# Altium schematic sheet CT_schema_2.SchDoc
size 591 x 347 mm
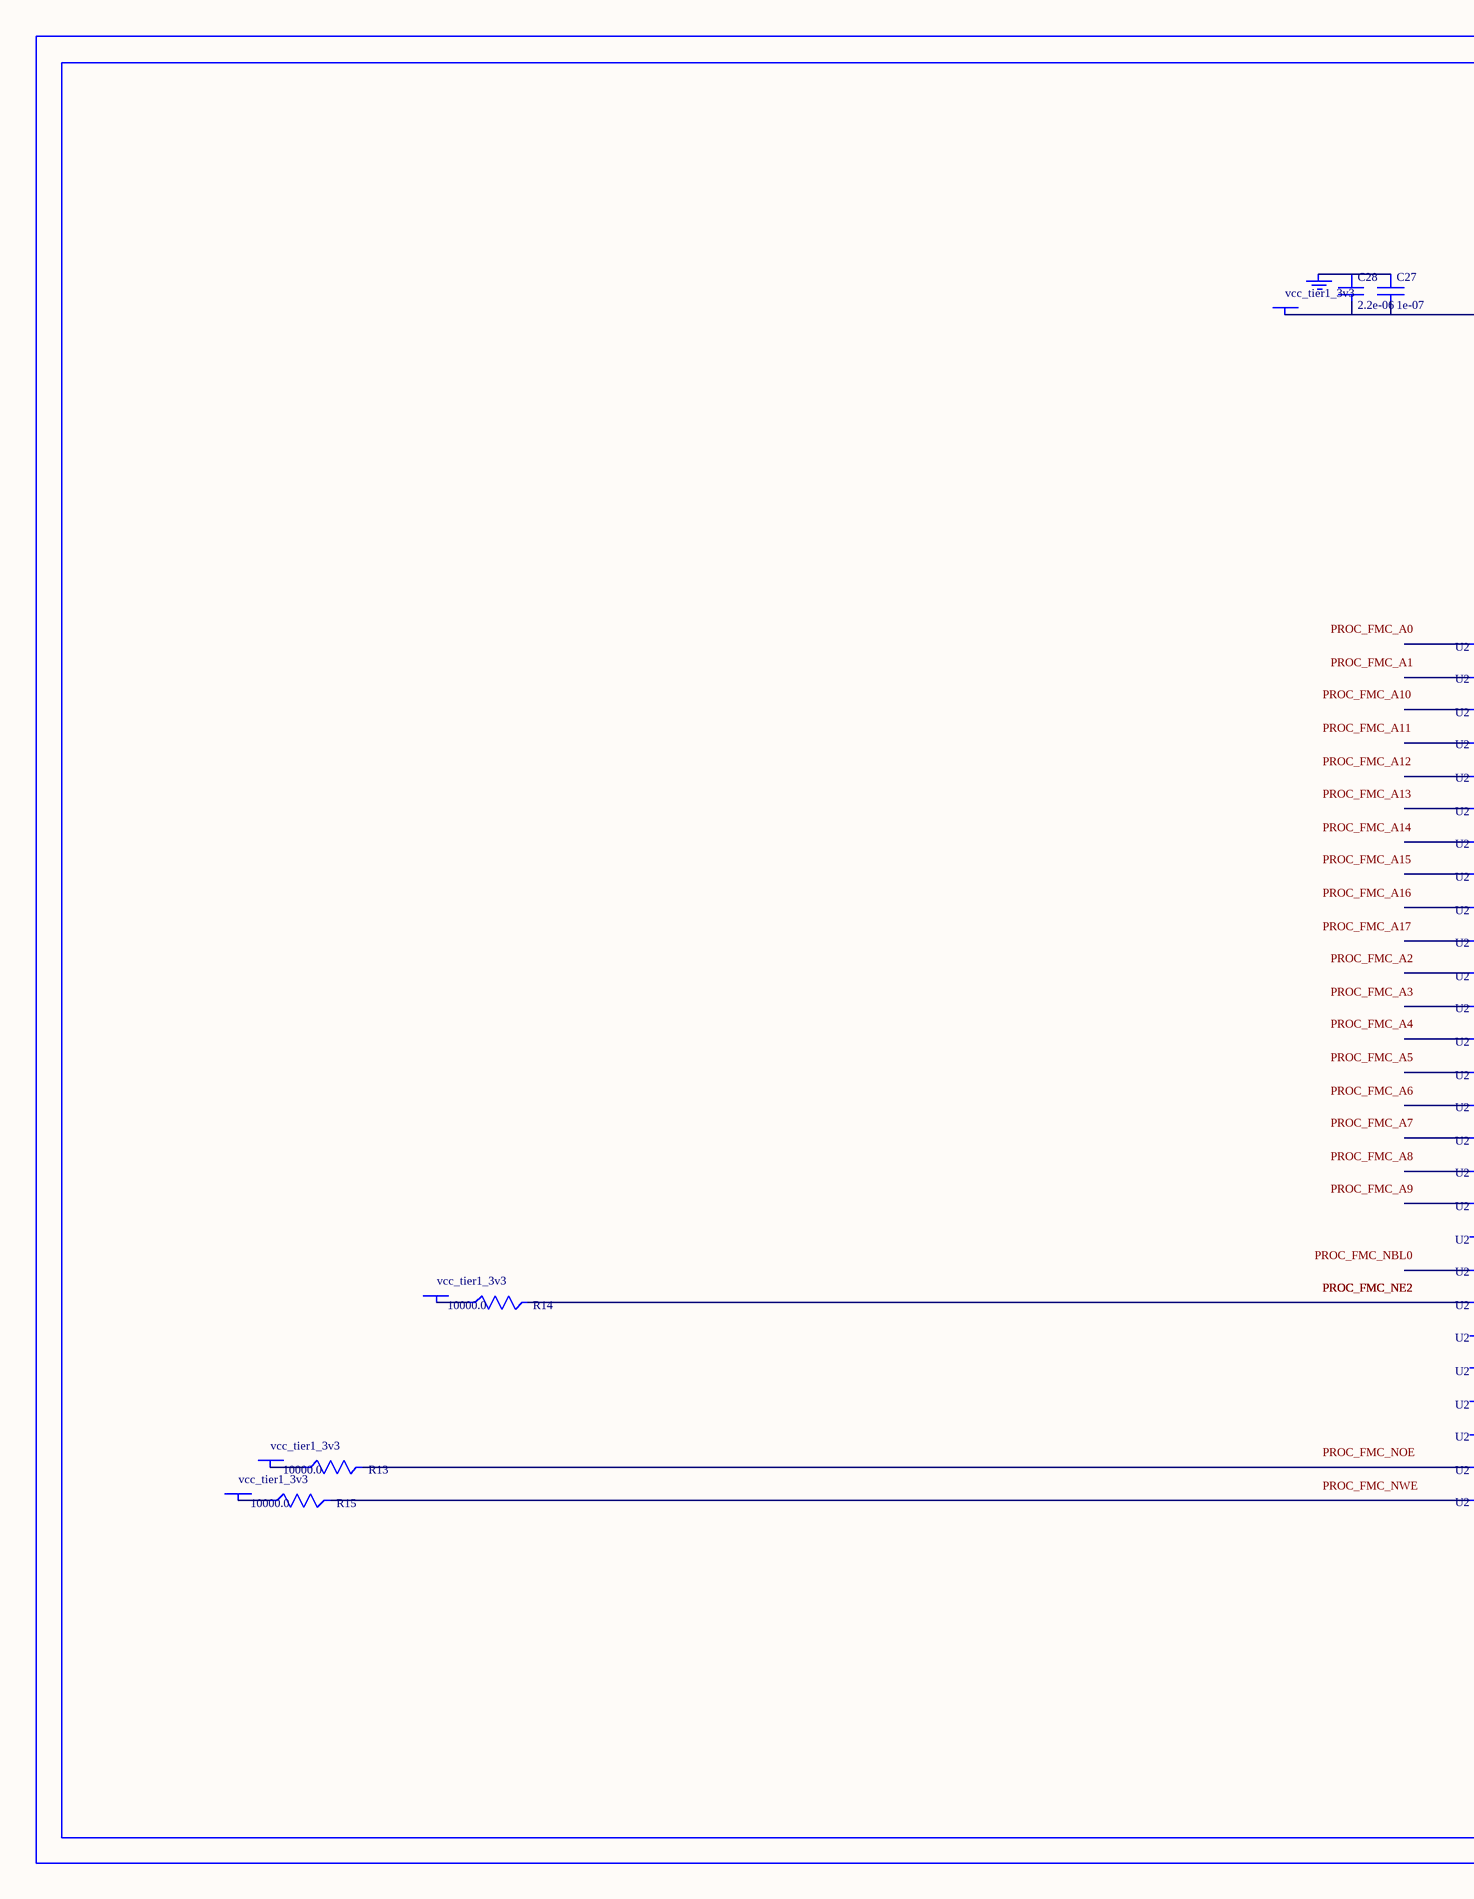
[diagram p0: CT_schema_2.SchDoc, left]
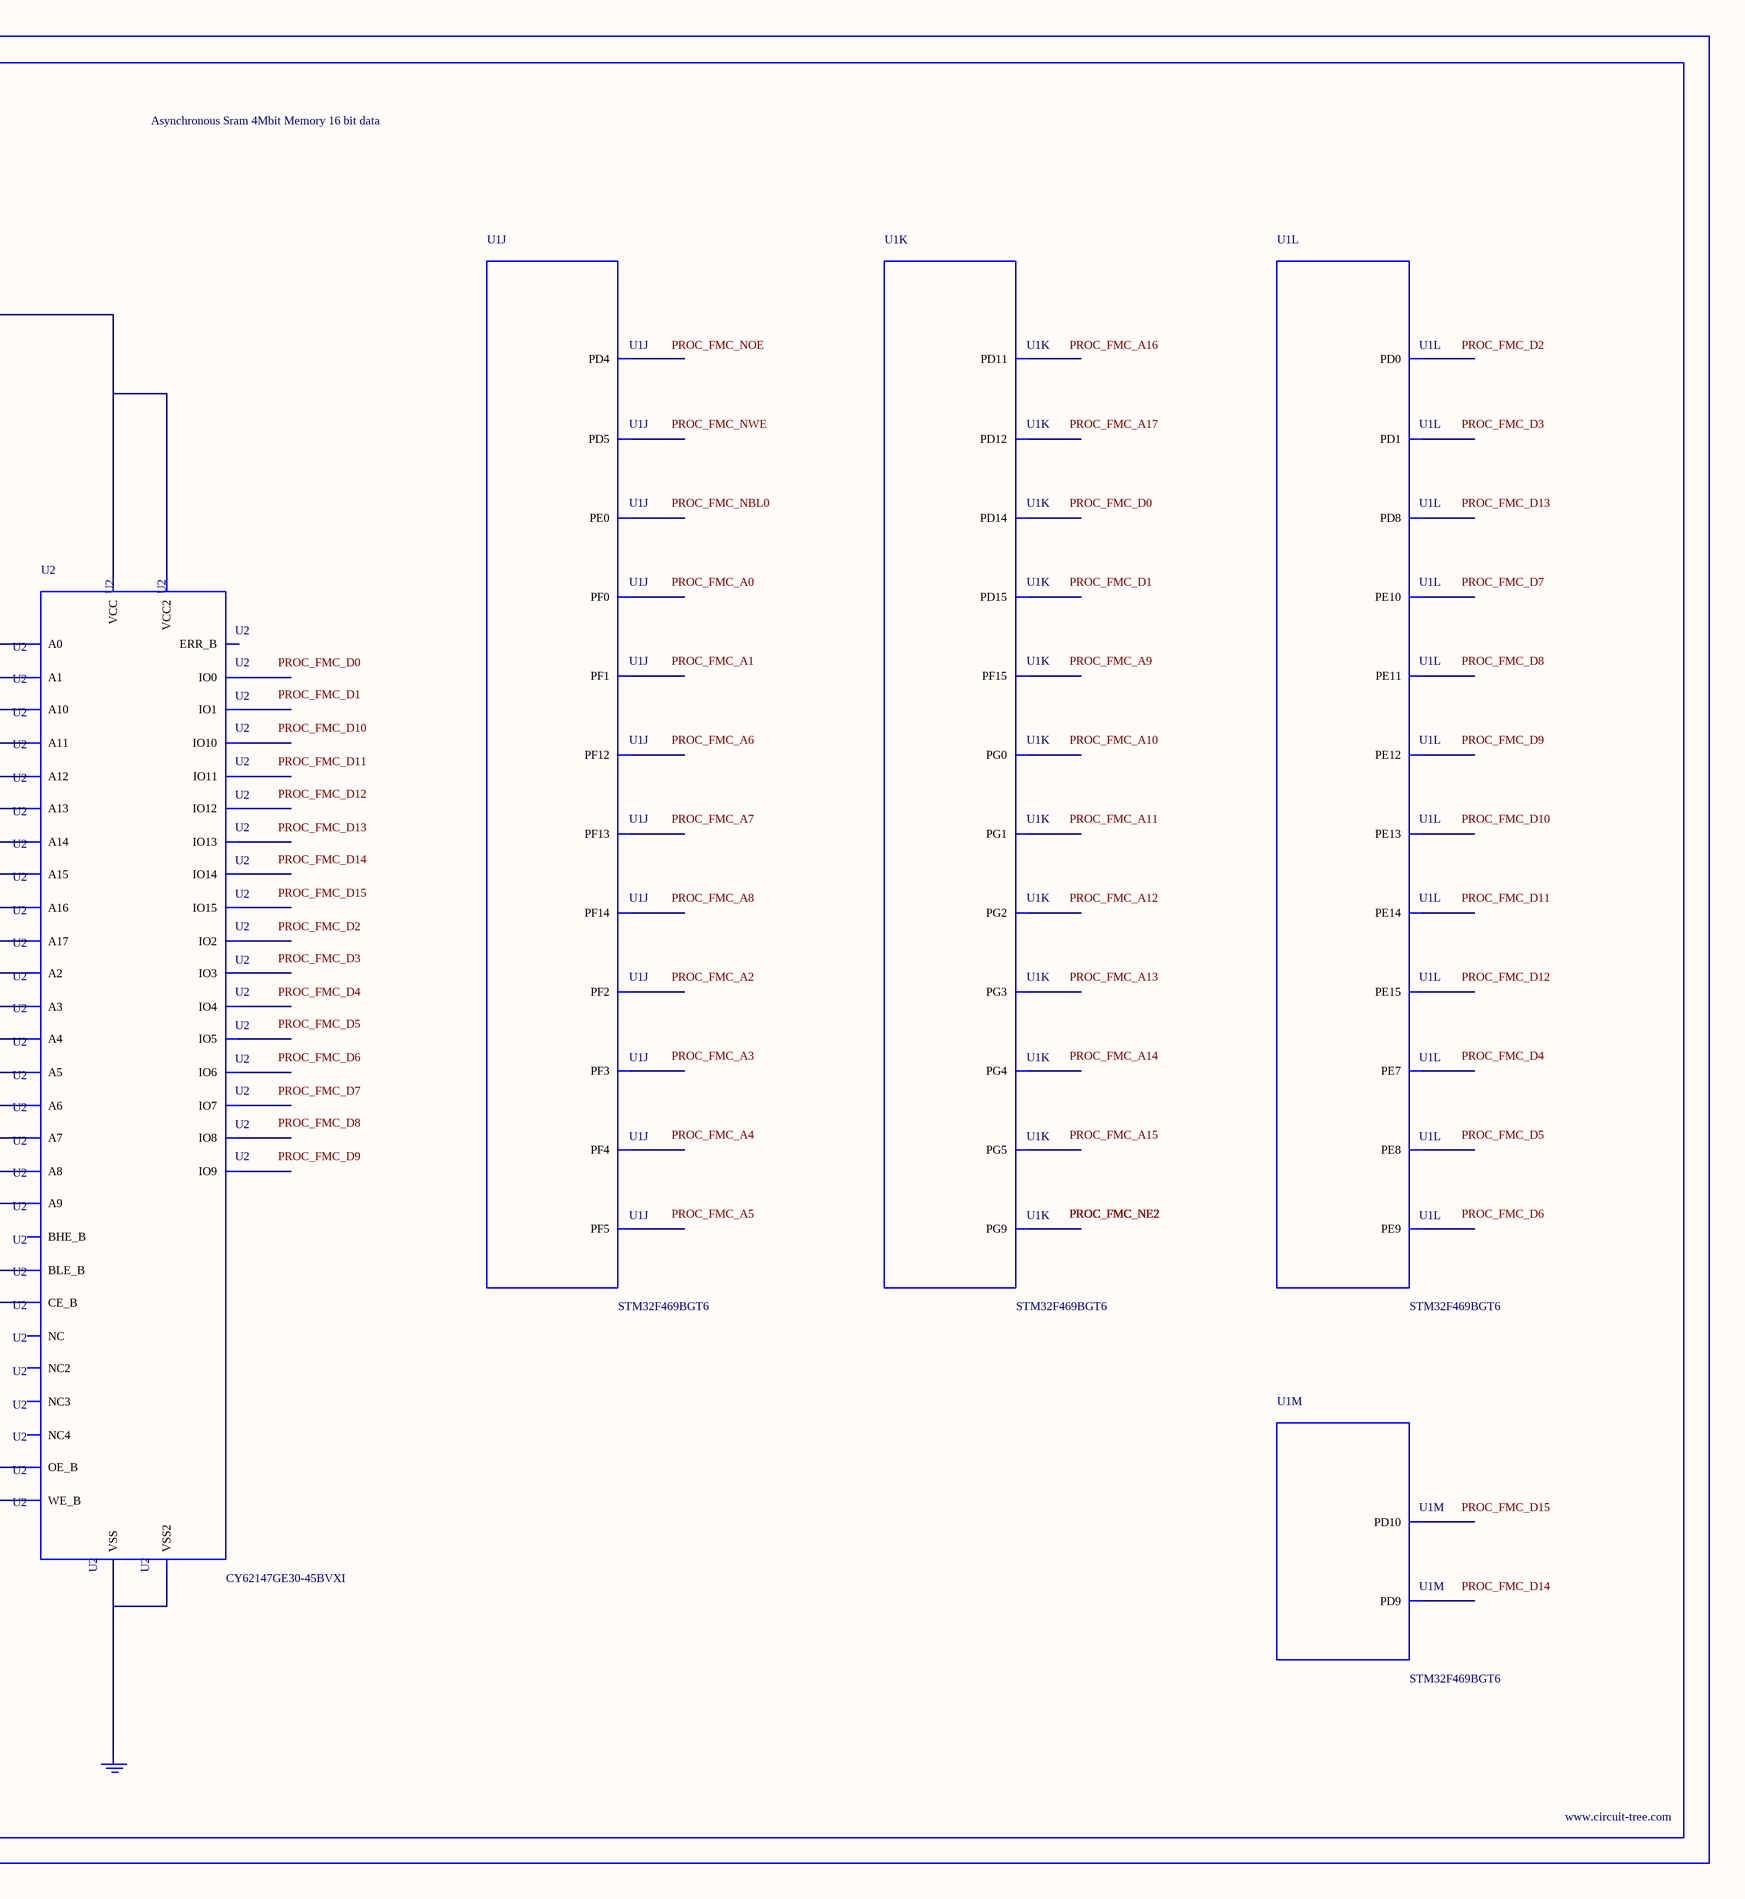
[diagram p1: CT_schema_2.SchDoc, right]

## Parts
BORDER1  (no value)
C27  1e-07  [C0402]
C28  2.2e-06  [C0603]
GND_INSTANCE_1_0  (no value)
GND_INSTANCE_1_1  (no value)
POWER_INSTANCE_1_0  vcc_tier1_3v3
POWER_INSTANCE_1_1  vcc_tier1_3v3
POWER_INSTANCE_1_2  vcc_tier1_3v3
POWER_INSTANCE_1_3  vcc_tier1_3v3
R13  10000.0  [R0603]
R14  10000.0  [R0603]
R15  10000.0  [R0603]
U1  STM32F469BGT6  [LQFP208]  (parts J,K,L,M of 16)
U2  CY62147GE30-45BVXI  [VFBGA48]

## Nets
NetC27_1: C27.1 C28.1 GND_INSTANCE_1_0.0(GND)
NetC27_2: C27.2 C28.2 POWER_INSTANCE_1_0.0(PWR) U2.D6(VCC) U2.E1(VCC2)
NetGND_INSTANCE_1_1_0: GND_INSTANCE_1_1.0(GND) U2.D1(VSS) U2.E6(VSS2)
NetPOWER_INSTANCE_1_1_0: POWER_INSTANCE_1_1.0(PWR) R13.1
NetPOWER_INSTANCE_1_2_0: POWER_INSTANCE_1_2.0(PWR) R14.1
NetPOWER_INSTANCE_1_3_0: POWER_INSTANCE_1_3.0(PWR) R15.1
NetR13_2: R13.2 U2.A2(OE_B)
NetR14_2: R14.2 U2.B5(CE_B)
NetR15_2: R15.2 U2.G5(WE_B)

Not connected (* = marked no-connect by the designer): U1 16(PF0) 17(PF1) 18(PF2) 22(PF3) 23(PF4) 24(PF5) 71(PF12) 74(PF13) 75(PF14) 76(PF15) 77(PG0) 78(PG1) 79(PE7) 80(PE8) 81(PE9) 84(PE10) 85(PE11) 86(PE12) 87(PE13) 88(PE14) 89(PE15) 108(PD8) 109(PD9) 110(PD10) 111(PD11) 112(PD12) 116(PD14) 117(PD15) 129(PG2) 130(PG3) 131(PG4) 132(PG5) 164(PD0) 165(PD1) 168(PD4) 169(PD5) 178(PG9) 200(PE0); U2 A1(BLE_B) A3(A0) A4(A1) A5(A2) A6(NC) B1(IO8) B2(BHE_B) B3(A3) B4(A4) B6(IO0) C1(IO9) C2(IO10) C3(A5) C4(A6) C5(IO1) C6(IO2) D2(IO11) D3(A17) D4(A7) D5(IO3) E2(IO12) E3(ERR_B) E4(A16) E5(IO4) F1(IO14) F2(IO13) F3(A14) F4(A15) F5(IO5) F6(IO6) G1(IO15) G2(NC2) G3(A12) G4(A13) G6(IO7) H1(NC3) H2(A8) H3(A9) H4(A10) H5(A11) H6(NC4)

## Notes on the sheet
- Labels drawn without touching a wire or pin: PROC_FMC_A0, PROC_FMC_A1, PROC_FMC_A2, PROC_FMC_A3, PROC_FMC_A4, PROC_FMC_A5, PROC_FMC_A6, PROC_FMC_A7, PROC_FMC_A8, PROC_FMC_A9, PROC_FMC_A10, PROC_FMC_A11, PROC_FMC_A12, PROC_FMC_A13, PROC_FMC_A14, PROC_FMC_A15, PROC_FMC_A16, PROC_FMC_A17, PROC_FMC_D0, PROC_FMC_D1, PROC_FMC_D2, PROC_FMC_D3, PROC_FMC_D4, PROC_FMC_D5, PROC_FMC_D6, PROC_FMC_D7, PROC_FMC_D8, PROC_FMC_D9, PROC_FMC_D10, PROC_FMC_D11, PROC_FMC_D12, PROC_FMC_D13, PROC_FMC_D14, PROC_FMC_D15, PROC_FMC_NBL0, PROC_FMC_NOE, PROC_FMC_NWE

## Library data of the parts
BORDER1 = BORDER_PAGE1
C27 = C0402C104K3RACTU
C28 = C0603C225K8RACTU
GND_INSTANCE_1_0 GND_INSTANCE_1_1 = GND
POWER_INSTANCE_1_0-POWER_INSTANCE_1_3 = PWR
R13-R15 = RC0603JR-0710KL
